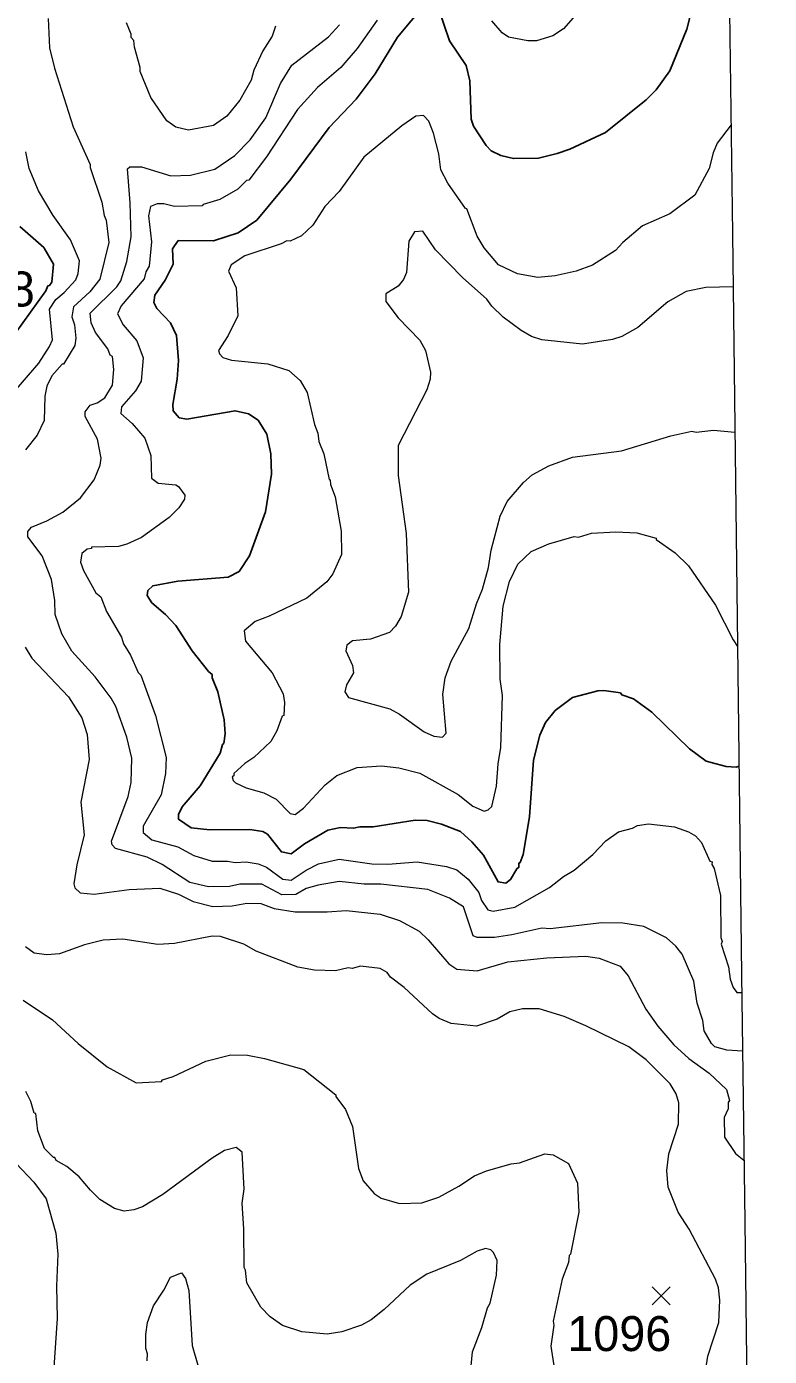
# Model space of a CAD drawing. Extents: x 265.7 to 292.1, y 7676.2 to 7704.2.
# Drawn here: x 290.402 to 292.102, y 7680.733 to 7683.775 of the extents above; entities that cross this region are included whole.
import ezdxf
from ezdxf.enums import TextEntityAlignment as Align

# ---------------------------------------------------------------- set-up
doc = ezdxf.new("R2010")
doc.units = 0
doc.header["$LTSCALE"] = 0.032
for name, color, linetype, lineweight in [('1', 7, 'Continuous', 25), ('2', 7, 'Continuous', 13), ('21', 7, 'Continuous', 25), ('63', 7, 'Continuous', 25)]:
    doc.layers.add(name, color=color, linetype=linetype, lineweight=lineweight)
doc.layers.add('61', color=7, linetype='Continuous')

msp = doc.modelspace()

# ---------------------------------------------------------------- linework, layer by layer
at = {"layer": '1'}
for points in [[(291.3135, 7683.8263), (291.2512, 7683.7513), (291.2002, 7683.6676), (291.1563, 7683.6093), (291.0948, 7683.5447), (291.0071, 7683.4266), (290.9289, 7683.3324), (290.8866, 7683.3037), (290.8299, 7683.2853), (290.7493, 7683.2861), (290.7358, 7683.267), (290.7374, 7683.2319), (290.719, 7683.1952), (290.6959, 7683.1608), (290.6935, 7683.1441), (290.7006, 7683.1305), (290.7318, 7683.0978), (290.7453, 7683.0691), (290.7501, 7683.0116), (290.7469, 7682.9685), (290.7366, 7682.9111), (290.7374, 7682.8967), (290.7517, 7682.8807), (290.7693, 7682.8776), (290.8794, 7682.8967), (290.9097, 7682.8895), (290.9321, 7682.8752), (290.952, 7682.8432), (290.9608, 7682.7978), (290.9624, 7682.7515), (290.9488, 7682.6653), (290.9121, 7682.5648), (290.889, 7682.5289), (290.8634, 7682.5161), (290.7485, 7682.5065), (290.6911, 7682.4961), (290.6799, 7682.4858), (290.6783, 7682.4738), (290.6887, 7682.457), (290.7198, 7682.4307), (290.7437, 7682.4052), (290.7812, 7682.3477), (290.8187, 7682.2998), (290.8267, 7682.2935), (290.8267, 7682.2855), (290.8395, 7682.2536), (290.8547, 7682.1897), (290.857, 7682.1578), (290.8539, 7682.1355), (290.8507, 7682.1331), (290.8451, 7682.1131), (290.7996, 7682.0389), (290.7581, 7681.9902), (290.7501, 7681.9727), (290.7501, 7681.9623), (290.7788, 7681.9423), (290.8219, 7681.9376), (290.9129, 7681.9384), (290.9432, 7681.9344), (290.9536, 7681.928), (290.9855, 7681.8873), (291.0079, 7681.8833), (291.0382, 7681.9056)], [(291.9255, 7683.8176), (291.9135, 7683.7697), (291.8744, 7683.6739), (291.8433, 7683.6308), (291.8202, 7683.6077), (291.7268, 7683.5335), (291.6454, 7683.4952), (291.6167, 7683.4848), (291.5736, 7683.4744), (291.5162, 7683.4736), (291.4874, 7683.4808), (291.4651, 7683.4912), (291.4539, 7683.5032), (291.4252, 7683.5479), (291.4196, 7683.5638), (291.4164, 7683.6516), (291.4084, 7683.6867), (291.3701, 7683.7426), (291.3438, 7683.8192)], [(290.387, 7683.318), (290.4413, 7683.2702), (290.4637, 7683.2319), (290.4597, 7683.1904), (290.4549, 7683.1832), (290.4509, 7683.1824), (290.4461, 7683.1712), (290.2873, 7682.951)], [(291.2912, 7681.9599), (291.3191, 7681.9591), (291.3518, 7681.9511), (291.3949, 7681.9344), (291.4212, 7681.9104), (291.4475, 7681.8801), (291.4811, 7681.8187), (291.4986, 7681.8163), (291.5098, 7681.8243), (291.5241, 7681.849), (291.5289, 7681.8522), (291.5289, 7681.8618), (291.5321, 7681.8634), (291.5385, 7681.8817), (291.5529, 7681.9679), (291.5624, 7682.0972), (291.5768, 7682.1546), (291.5896, 7682.1833), (291.6119, 7682.2113), (291.6518, 7682.2408), (291.7093, 7682.2559), (291.7236, 7682.2567), (291.7611, 7682.2512), (291.7643, 7682.2464), (291.7915, 7682.2376), (291.833, 7682.2073), (291.9191, 7682.1235), (291.9574, 7682.0948), (292.0029, 7682.0828), (292.0261, 7682.0812), (292.0327, 7682.0832)], [(291.0382, 7681.9056), (291.0917, 7681.9368), (291.1204, 7681.9431), (291.1507, 7681.9415), (291.1651, 7681.9447), (291.1954, 7681.9447), (291.2912, 7681.9599)]]:
    msp.add_lwpolyline(points, dxfattribs=at)
at = {"layer": '2'}
for points in [[(290.4517, 7683.7936), (290.4549, 7683.7266), (290.4661, 7683.6803), (290.5091, 7683.5463), (290.5474, 7683.4601), (290.5474, 7683.4529), (290.5746, 7683.3739), (290.5794, 7683.3436), (290.5841, 7683.3324), (290.5905, 7683.2813), (290.5698, 7683.1975), (290.5466, 7683.1688), (290.5099, 7683.1345), (290.5059, 7683.1114), (290.5115, 7683.093), (290.5147, 7683.0627), (290.5123, 7683.0459), (290.4868, 7683.0028), (290.4836, 7683.0028), (290.4597, 7682.9765), (290.4485, 7682.9526), (290.4437, 7682.9302), (290.4421, 7682.8744), (290.4262, 7682.8409), (290.3998, 7682.8073)], [(291.2042, 7683.7904), (291.1587, 7683.725), (291.1212, 7683.6819), (291.0677, 7683.6364), (291.0222, 7683.5854), (290.9512, 7683.4776)], [(291.6534, 7683.7952), (291.6311, 7683.7705), (291.6063, 7683.7545), (291.5688, 7683.7426), (291.5497, 7683.7426), (291.505, 7683.7513), (291.4906, 7683.7609), (291.4667, 7683.7888)], [(292.0408, 7681.4313), (292.0045, 7681.4341), (291.9774, 7681.4412), (291.9694, 7681.4492), (291.9527, 7681.4779), (291.9495, 7681.5019), (291.9367, 7681.5418), (291.9295, 7681.5921), (291.9024, 7681.6535), (291.888, 7681.6718), (291.8665, 7681.691), (291.8146, 7681.7165), (291.7667, 7681.7245), (291.7189, 7681.7253), (291.6008, 7681.7117), (291.5816, 7681.7133), (291.513, 7681.6974), (291.4731, 7681.6918), (291.4332, 7681.6918), (291.4244, 7681.6958), (291.4021, 7681.762), (291.3701, 7681.782), (291.3207, 7681.8011), (291.213, 7681.8139), (291.1746, 7681.8139), (291.1172, 7681.8195), (291.0693, 7681.8115), (291.0422, 7681.8035), (291.0182, 7681.7899), (290.9863, 7681.7891), (290.9408, 7681.8139), (290.8906, 7681.8139), (290.8666, 7681.8083), (290.8188, 7681.8075), (290.7757, 7681.8171), (290.7126, 7681.8586), (290.6783, 7681.8753), (290.6057, 7681.8953), (290.5977, 7681.9033), (290.5969, 7681.912), (290.6344, 7682.0142), (290.6416, 7682.0461), (290.6432, 7682.102), (290.632, 7682.1498), (290.6065, 7682.22), (290.5961, 7682.2392), (290.5594, 7682.2879), (290.5059, 7682.3469), (290.4828, 7682.386), (290.4677, 7682.4307), (290.4669, 7682.4626), (290.4589, 7682.5105), (290.4381, 7682.5648), (290.4054, 7682.6079), (290.4054, 7682.6206), (290.4134, 7682.6302), (290.4485, 7682.6446), (290.4852, 7682.6645), (290.5259, 7682.6972), (290.557, 7682.7387), (290.5706, 7682.7722), (290.573, 7682.7882), (290.5642, 7682.8313), (290.5363, 7682.8832), (290.5363, 7682.8943), (290.5474, 7682.9095), (290.5634, 7682.9151), (290.581, 7682.9262), (290.5985, 7682.955), (290.6017, 7682.9909), (290.5985, 7683.0204), (290.5937, 7683.0236), (290.5881, 7683.038), (290.5602, 7683.0755), (290.5498, 7683.0978), (290.5474, 7683.1201), (290.6089, 7683.18), (290.6177, 7683.1936), (290.632, 7683.2382), (290.6416, 7683.2941), (290.6392, 7683.3723), (290.6328, 7683.4497), (290.6384, 7683.4545), (290.6655, 7683.4545), (290.7326, 7683.4337), (290.7773, 7683.4353), (290.8331, 7683.4489), (290.8786, 7683.4808), (290.9137, 7683.5167), (290.9496, 7683.567), (290.9831, 7683.6452), (291.0095, 7683.6875), (291.0933, 7683.7521), (291.118, 7683.7793)], [(290.972, 7683.7761), (290.964, 7683.7537), (290.9432, 7683.7202), (290.9225, 7683.6755), (290.9161, 7683.6532), (290.8906, 7683.6069), (290.8602, 7683.5702), (290.8299, 7683.5494), (290.7725, 7683.5383), (290.7437, 7683.5455), (290.723, 7683.5598), (290.6863, 7683.6133), (290.6623, 7683.6723), (290.6623, 7683.6819), (290.6488, 7683.7282), (290.648, 7683.7434), (290.6416, 7683.7505), (290.6416, 7683.7577), (290.6312, 7683.7841)], [(292.0144, 7683.5504), (291.9826, 7683.5091), (291.9736, 7683.4869), (291.9645, 7683.4507), (291.9317, 7683.3899), (291.8745, 7683.3468), (291.8114, 7683.3196), (291.7667, 7683.2813), (291.75, 7683.263), (291.6973, 7683.2295), (291.6598, 7683.2159), (291.6119, 7683.2055), (291.572, 7683.2015), (291.5257, 7683.2095), (291.4819, 7683.2303), (291.4491, 7683.2694), (291.4332, 7683.2957), (291.41, 7683.3587), (291.4068, 7683.3595), (291.3662, 7683.417), (291.3502, 7683.4481), (291.3454, 7683.484), (291.3334, 7683.5319), (291.3231, 7683.559), (291.3103, 7683.5718), (291.2927, 7683.5702), (291.2608, 7683.5486), (291.1738, 7683.4768), (291.1172, 7683.3978), (291.0845, 7683.3635), (291.0573, 7683.3212), (291.031, 7683.2965), (291.0055, 7683.2845), (290.9975, 7683.2853), (290.9847, 7683.2781), (290.9017, 7683.251), (290.8706, 7683.2303), (290.8642, 7683.2159), (290.8818, 7683.1776), (290.8858, 7683.1138), (290.8634, 7683.0691), (290.8411, 7683.0348), (290.8435, 7683.0268), (290.8515, 7683.0188), (290.8714, 7683.0124), (290.9544, 7683.0036), (291.0023, 7682.9885), (291.0286, 7682.9661), (291.0446, 7682.9382), (291.0613, 7682.8648), (291.0685, 7682.8457), (291.0709, 7682.8265), (291.0821, 7682.7978), (291.0948, 7682.7395), (291.0972, 7682.7387), (291.098, 7682.7276), (291.1084, 7682.6996), (291.122, 7682.6214), (291.1228, 7682.568), (291.1028, 7682.5233), (291.0893, 7682.5049), (291.0438, 7682.4682), (290.9576, 7682.4267), (290.9257, 7682.4147), (290.9001, 7682.3932), (290.9033, 7682.3693), (290.964, 7682.2974), (290.9895, 7682.2488), (290.9927, 7682.2296), (290.9911, 7682.1993), (290.9871, 7682.1977), (290.9751, 7682.1642), (290.9608, 7682.1403), (290.9225, 7682.1035), (290.9017, 7682.09), (290.8762, 7682.0668), (290.8762, 7682.0613), (290.873, 7682.0589), (290.8746, 7682.0509), (290.8802, 7682.0453), (290.9049, 7682.0341), (290.9448, 7682.0222), (290.9736, 7682.0078), (291.0055, 7681.9751), (291.0166, 7681.9727), (291.0358, 7681.9878), (291.0853, 7682.0405), (291.1124, 7682.062), (291.1587, 7682.0804), (291.2145, 7682.0844), (291.2544, 7682.0796), (291.3023, 7682.0676), (291.3901, 7682.019), (291.4236, 7681.9918), (291.4491, 7681.9807)], [(290.3264, 7682.8855), (290.4301, 7683.0052), (290.4549, 7683.0435), (290.4613, 7683.0587), (290.4549, 7683.1289), (290.4692, 7683.1513), (290.4884, 7683.1672), (290.5147, 7683.196), (290.5203, 7683.2103), (290.5235, 7683.2398), (290.5028, 7683.2877), (290.4629, 7683.3436), (290.4293, 7683.3994), (290.4078, 7683.4505), (290.4006, 7683.4888)], [(290.9512, 7683.4776), (290.9105, 7683.4242), (290.9057, 7683.4234), (290.8858, 7683.4034), (290.8443, 7683.3795), (290.806, 7683.3683), (290.8044, 7683.3651)], [(290.8044, 7683.3651), (290.7406, 7683.3635), (290.7166, 7683.3699), (290.7007, 7683.3699), (290.6855, 7683.3635), (290.6815, 7683.3428), (290.6879, 7683.2829), (290.6831, 7683.2271), (290.6751, 7683.2143), (290.6711, 7683.1983), (290.6185, 7683.1369), (290.6105, 7683.1186), (290.6232, 7683.093), (290.6544, 7683.0563), (290.6687, 7683.018), (290.6647, 7682.9645), (290.6512, 7682.9422), (290.6193, 7682.9055), (290.6177, 7682.8903), (290.644, 7682.8672), (290.6727, 7682.8337), (290.6863, 7682.7946), (290.6879, 7682.7427), (290.703, 7682.7307), (290.7437, 7682.7275), (290.7501, 7682.7236), (290.7645, 7682.7036), (290.7637, 7682.694), (290.7509, 7682.6749), (290.7286, 7682.6525), (290.6655, 7682.6063), (290.632, 7682.5911), (290.6129, 7682.5863), (290.5506, 7682.5847), (290.5506, 7682.5815), (290.5411, 7682.5799), (290.5283, 7682.5704), (290.5259, 7682.5504), (290.5323, 7682.5313), (290.561, 7682.4802), (290.5722, 7682.4706), (290.5849, 7682.4371), (290.6193, 7682.3788), (290.624, 7682.3637), (290.64, 7682.3373), (290.6576, 7682.2982), (290.6639, 7682.2919), (290.6975, 7682.1993), (290.7214, 7682.1035), (290.7198, 7682.0668), (290.7102, 7682.0182), (290.6687, 7681.9463), (290.6687, 7681.932), (290.6887, 7681.9152), (290.7485, 7681.8993), (290.7852, 7681.8793), (290.8267, 7681.8665), (290.8618, 7681.8665), (290.8794, 7681.8634), (290.9049, 7681.8649), (290.9321, 7681.8602), (290.9512, 7681.8522), (290.9887, 7681.8251), (291.0079, 7681.8227), (291.0422, 7681.8458), (291.0701, 7681.8602), (291.1172, 7681.8705), (291.1922, 7681.8602), (291.2289, 7681.8594), (291.2959, 7681.8649), (291.363, 7681.8538), (291.3869, 7681.8466), (291.4124, 7681.8251), (291.4372, 7681.7947), (291.4436, 7681.7764), (291.4579, 7681.7548), (291.4699, 7681.7516), (291.5194, 7681.7612), (291.5992, 7681.8059), (291.6311, 7681.8314), (291.655, 7681.8458), (291.6981, 7681.8817), (291.7276, 7681.9128), (291.7572, 7681.9336), (291.7891, 7681.9416), (291.8002, 7681.9479), (291.8258, 7681.9519), (291.8848, 7681.9447), (291.9168, 7681.9336), (291.9327, 7681.924), (291.9471, 7681.9088), (291.9662, 7681.8665), (291.971, 7681.865), (291.9702, 7681.8586), (291.9758, 7681.8498)], [(292.019, 7683.18), (291.9566, 7683.1786), (291.9118, 7683.1694), (291.8697, 7683.1457), (291.801, 7683.0874), (291.7643, 7683.0667), (291.7428, 7683.0595), (291.6742, 7683.0491), (291.5816, 7683.0587), (291.5577, 7683.0667), (291.5337, 7683.0802), (291.493, 7683.1106), (291.4667, 7683.1361), (291.4555, 7683.1521), (291.3997, 7683.2015), (291.3382, 7683.2646), (291.3087, 7683.3077), (291.2896, 7683.3061), (291.2768, 7683.2845), (291.272, 7683.2127), (291.2648, 7683.1968), (291.2528, 7683.1816), (291.2241, 7683.164), (291.2241, 7683.1465), (291.2528, 7683.109), (291.3023, 7683.0579), (291.3151, 7683.0348), (291.3263, 7682.9845), (291.3255, 7682.9685), (291.3183, 7682.9446), (291.2528, 7682.8169), (291.2528, 7682.7483), (291.2712, 7682.6158), (291.276, 7682.4818), (291.2592, 7682.4259), (291.2465, 7682.4036), (291.2329, 7682.3892), (291.189, 7682.374), (291.1483, 7682.3701), (291.1348, 7682.3605), (291.1331, 7682.3477), (291.1483, 7682.3142), (291.1507, 7682.2974), (291.1347, 7682.2695), (291.1308, 7682.2536), (291.1387, 7682.2408), (291.2337, 7682.2145), (291.256, 7682.2025), (291.3119, 7682.1618), (291.3342, 7682.1522), (291.3542, 7682.1498), (291.3622, 7682.1594), (291.355, 7682.2472), (291.3598, 7682.2855), (291.3741, 7682.3238), (291.414, 7682.3988), (291.4316, 7682.4546), (291.4459, 7682.4882), (291.4595, 7682.5384), (291.4651, 7682.5775), (291.4858, 7682.6557), (291.5018, 7682.6893), (291.5393, 7682.7323), (291.5593, 7682.7499), (291.5976, 7682.7706), (291.6518, 7682.7906), (291.7635, 7682.8049), (291.8769, 7682.8393), (291.9247, 7682.8496), (291.9343, 7682.848), (291.9742, 7682.852), (292.0231, 7682.8478)], [(291.4914, 7682.2456), (291.4858, 7682.2823), (291.485, 7682.3621), (291.493, 7682.4499), (291.5074, 7682.5057), (291.5265, 7682.5456), (291.5569, 7682.5743), (291.5976, 7682.5919), (291.655, 7682.6086), (291.6654, 7682.6078), (291.6949, 7682.6166), (291.7508, 7682.6198), (291.7987, 7682.6174), (291.8433, 7682.6055), (291.8433, 7682.6023), (291.8864, 7682.5719), (291.9167, 7682.5416), (291.979, 7682.4515), (292.0189, 7682.3725), (292.0292, 7682.3574)], [(290.399, 7682.3557), (290.4142, 7682.331), (290.498, 7682.2424), (290.5283, 7682.1945), (290.5411, 7682.1562), (290.5458, 7682.0988), (290.5267, 7682.0014), (290.5339, 7681.9264), (290.5171, 7681.8578), (290.5107, 7681.8147), (290.5123, 7681.8051), (290.5251, 7681.7939)], [(291.4491, 7681.9807), (291.4587, 7681.9838), (291.4667, 7681.991), (291.4779, 7682.0381), (291.4811, 7682.0892), (291.4874, 7682.1259), (291.4914, 7682.2456)], [(291.9758, 7681.8498), (291.9902, 7681.7876), (291.991, 7681.6918), (291.9941, 7681.6822), (291.9918, 7681.6766), (292.0085, 7681.6248), (292.0125, 7681.596)], [(290.5251, 7681.7939), (290.557, 7681.7907), (290.6368, 7681.8011), (290.707, 7681.8043), (290.7501, 7681.7907), (290.7836, 7681.774), (290.8283, 7681.7628)], [(290.8283, 7681.7628), (290.873, 7681.7644), (290.9065, 7681.77), (290.9385, 7681.7692), (290.9688, 7681.758), (291.0167, 7681.75), (291.0901, 7681.75), (291.1332, 7681.7532), (291.2114, 7681.7453), (291.256, 7681.7309), (291.3007, 7681.7062), (291.3215, 7681.6862), (291.3685, 7681.6311), (291.3869, 7681.6192), (291.4332, 7681.6152), (291.5034, 7681.6359), (291.5928, 7681.6455), (291.6822, 7681.6487), (291.7125, 7681.6447), (291.7604, 7681.6264), (291.7787, 7681.604), (291.8194, 7681.5274), (291.8465, 7681.4891), (291.8832, 7681.446), (291.9175, 7681.4149), (291.9646, 7681.3814), (292.0037, 7681.3439), (292.0109, 7681.3191), (292.0077, 7681.3144), (292.0077, 7681.3), (291.9989, 7681.28), (291.9997, 7681.2346), (292.0245, 7681.1979), (292.0439, 7681.1822)], [(291.9543, 7680.6896), (291.9614, 7680.7342), (291.9862, 7680.8108), (291.9886, 7680.8619), (291.9854, 7680.8906), (291.979, 7680.9098), (291.9183, 7681.0247), (291.8936, 7681.063), (291.8705, 7681.1205), (291.8673, 7681.1588), (291.8721, 7681.1971), (291.8944, 7681.2649), (291.8952, 7681.3136), (291.8888, 7681.3343), (291.8753, 7681.3567), (291.8202, 7681.4117), (291.7803, 7681.4412), (291.6822, 7681.4899), (291.6327, 7681.5107), (291.5752, 7681.5282), (291.5369, 7681.5282), (291.5082, 7681.5218), (291.4795, 7681.5051), (291.4316, 7681.4891), (291.3741, 7681.4947), (291.3462, 7681.5067), (291.331, 7681.517), (291.2664, 7681.5769), (291.2353, 7681.6008), (291.2273, 7681.6112), (291.2114, 7681.6208), (291.1667, 7681.6264), (291.1475, 7681.6208), (291.1379, 7681.6224), (291.1092, 7681.6152), (291.0613, 7681.6168), (291.023, 7681.624), (290.9273, 7681.6607), (290.8993, 7681.6766), (290.8459, 7681.6942), (290.8267, 7681.695), (290.7406, 7681.6782), (290.7023, 7681.6758), (290.6225, 7681.6878), (290.5778, 7681.6854), (290.5347, 7681.675), (290.4772, 7681.6543), (290.4485, 7681.6519), (290.4198, 7681.6559), (290.3998, 7681.6702)], [(292.0125, 7681.596), (292.0189, 7681.5769), (292.0277, 7681.5657), (292.0391, 7681.5656)], [(290.3942, 7681.5482), (290.4613, 7681.5035), (290.5203, 7681.4492), (290.5865, 7681.3957), (290.6528, 7681.359), (290.711, 7681.3622), (290.7134, 7681.3662), (290.7374, 7681.3734), (290.8124, 7681.4085), (290.8698, 7681.4229), (290.9081, 7681.4221), (290.9464, 7681.4149), (291.0366, 7681.3894), (291.11, 7681.3319), (291.11, 7681.3279), (291.1324, 7681.2984), (291.1483, 7681.2593), (291.1619, 7681.1635), (291.1722, 7681.1348), (291.1978, 7681.1061), (291.2137, 7681.0957), (291.256, 7681.0829), (291.3071, 7681.0845), (291.3454, 7681.0973), (291.3917, 7681.1228), (291.4276, 7681.1468), (291.4547, 7681.158), (291.5114, 7681.1739), (291.5305, 7681.1763), (291.588, 7681.1971), (291.6071, 7681.1947), (291.6423, 7681.1747), (291.663, 7681.13), (291.6662, 7681.063), (291.647, 7680.9672), (291.6438, 7680.9641), (291.6422, 7680.9481), (291.6279, 7680.9098), (291.6071, 7680.814), (291.6087, 7680.8045), (291.6023, 7680.7566), (291.6135, 7680.6832)], [(290.4118, 7681.3168), (290.4006, 7681.3391)], [(290.4669, 7681.1883), (290.4637, 7681.1883), (290.4429, 7681.209), (290.4277, 7681.2497), (290.423, 7681.2888), (290.4198, 7681.2896), (290.4118, 7681.3168)], [(290.0064, 7681.122), (290.0543, 7681.1404), (290.1596, 7681.1635), (290.2043, 7681.1875), (290.2458, 7681.2298), (290.2698, 7681.2593), (290.2937, 7681.2641), (290.3073, 7681.2593), (290.3336, 7681.2314), (290.3783, 7681.1747), (290.419, 7681.1316), (290.4469, 7681.0941), (290.4692, 7681.0151), (290.474, 7680.9672), (290.4708, 7680.8938), (290.4724, 7680.8204), (290.4613, 7680.664)], [(291.4172, 7680.688), (291.4228, 7680.7438), (291.4444, 7680.7997), (291.4571, 7680.8444), (291.4635, 7680.8555), (291.4779, 7680.9194), (291.4795, 7680.9529), (291.4707, 7680.9712), (291.4643, 7680.9768), (291.4523, 7680.98), (291.4332, 7680.9744), (291.3949, 7680.9529), (291.3183, 7680.9218), (291.28, 7680.8962), (291.2209, 7680.8404), (291.1906, 7680.8172), (291.1683, 7680.8045), (291.1236, 7680.7893), (291.0901, 7680.7845), (291.0318, 7680.7893), (290.9879, 7680.8037), (290.96, 7680.8236), (290.9384, 7680.846), (290.9065, 7680.9018), (290.9033, 7680.9305), (290.9001, 7680.9369), (290.8993, 7681.0255), (290.8954, 7681.0838), (290.9001, 7681.1157), (290.8954, 7681.2003), (290.8818, 7681.2114), (290.8555, 7681.2042), (290.8267, 7681.1867), (290.7142, 7681.1037), (290.6671, 7681.0758), (290.648, 7681.0686), (290.6257, 7681.0654), (290.6033, 7681.0718), (290.5698, 7681.0925), (290.5482, 7681.1133), (290.5227, 7681.1444), (290.494, 7681.1675), (290.47, 7681.1819), (290.4669, 7681.1883)], [(290.6783, 7680.7231), (290.6791, 7680.739), (290.6751, 7680.7518), (290.6751, 7680.7837), (290.6791, 7680.8108), (290.6927, 7680.8492), (290.7166, 7680.8851), (290.7318, 7680.9146), (290.7565, 7680.9242), (290.7661, 7680.9114), (290.7733, 7680.8843), (290.7812, 7680.7582), (290.794, 7680.7135)]]:
    msp.add_lwpolyline(points, dxfattribs=at)
at = {"layer": '21'}
for p, q in [((291.8342, 7680.8929), (291.8754, 7680.8517)), ((291.8754, 7680.8929), (291.8342, 7680.8517))]:
    msp.add_line(p, q, dxfattribs=at)
at = {"layer": '63', "lineweight": 13}
msp.add_lwpolyline([(291.9681, 7687.2556), (291.9752, 7686.6906), (291.9822, 7686.1257), (291.9893, 7685.5608), (291.9963, 7684.9959), (292.0034, 7684.431), (292.0104, 7683.866), (292.0175, 7683.3011), (292.0245, 7682.7362), (292.0316, 7682.1713), (292.0386, 7681.6064), (292.0457, 7681.0414), (292.0527, 7680.4765), (292.0598, 7679.9116), (292.0668, 7679.3467), (292.0739, 7678.7818), (292.081, 7678.2168), (292.088, 7677.6519), (292.0951, 7677.087), (292.1022, 7676.5221)], dxfattribs=at)

# ---------------------------------------------------------------- texts
at = {"layer": '61'}
for s, p in [('1118', (290.3019, 7683.1351)), ('1096', (291.7586, 7680.7456))]:
    msp.add_text(s, height=0.08, dxfattribs=at).set_placement(p, align=Align.CENTER)

doc.saveas('drawing.dxf')
